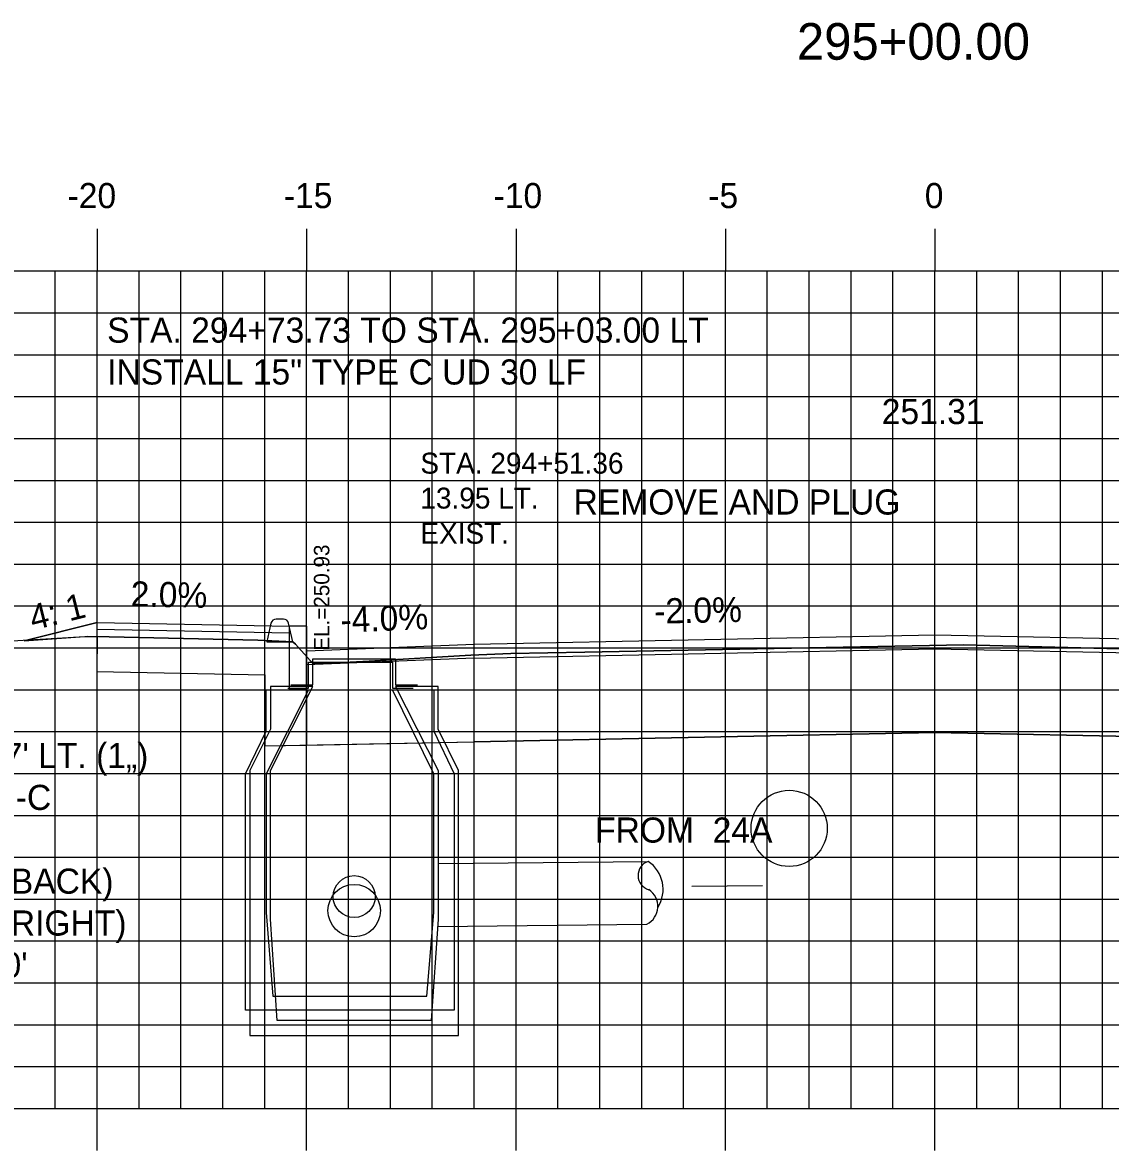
# Model space of a CAD drawing. Extents: x 859352 to 859522, y 366268 to 366378.
# Drawn here: x 859413.35 to 859439.32, y 366306.23 to 366333.17 of the extents above; entities that cross this region are included whole.
import ezdxf

# ---------------------------------------------------------------- set-up
doc = ezdxf.new("R2010")
doc.units = 0
for name, color, linetype in [('ANNOTATION', 7, 'Continuous'), ('D_Curb_Type_1_Lt', 7, 'Continuous'), ('D_Drainage_CB_TypeA1-B1', 7, 'Continuous'), ('D_Drainage_Text', 7, 'Continuous'), ('D_Roadway_Centerline_Text', 7, 'Continuous'), ('D_Roadway_Edge_Shoulder', 7, 'Continuous'), ('D_Roadway_FinishedGrade', 7, 'Continuous'), ('D_Roadway_Sidewalks_Paved', 7, 'Continuous'), ('D_Roadway_SubGrade', 7, 'Continuous'), ('D_Text_Monospaced', 7, 'Continuous'), ('D_Text_Standard', 7, 'Continuous'), ('H_V ANNOTATION', 7, 'Continuous'), ('JUNK COM EXC', 7, 'Continuous'), ('JUNK FILL', 7, 'Continuous'), ('MAJOR', 7, 'Continuous'), ('MINOR', 7, 'Continuous'), ('PDRAIN', 7, 'Continuous'), ('S_Curb_Type_3', 7, 'Continuous'), ('S_Drainage_CB', 7, 'Continuous'), ('S_Roadway_Centerline', 7, 'Continuous')]:
    doc.layers.add(name, color=color, linetype=linetype)

msp = doc.modelspace()

# ---------------------------------------------------------------- linework, layer by layer
at = {"layer": 'ANNOTATION'}
msp.add_line((859431.014, 366312.555), (859429.324, 366312.537), dxfattribs=at)
at = {"layer": 'D_Curb_Type_1_Lt'}
msp.add_lwpolyline([(859419.716, 366318.75), (859419.716, 366317.25), (859420.132, 366317.25), (859420.132, 366318.75)], close=True, dxfattribs=at)
at = {"layer": 'D_Drainage_CB_TypeA1-B1'}
for p, q in [((859419.264, 366317.311), (859419.264, 366316.294)), ((859419.264, 366315.31), (859420.281, 366317.311)), ((859420.281, 366317.311), (859419.264, 366317.311)), ((859423.267, 366317.311), (859422.25, 366317.311)), ((859422.25, 366317.311), (859423.267, 366315.31)), ((859423.267, 366316.294), (859423.267, 366317.311)), ((859419.264, 366316.294), (859418.772, 366315.31)), ((859423.759, 366315.31), (859423.267, 366316.294)), ((859418.772, 366315.31), (859418.772, 366308.976)), ((859419.264, 366311.754), (859419.264, 366315.31)), ((859423.267, 366315.31), (859423.267, 366311.754)), ((859423.759, 366308.976), (859423.759, 366315.31)), ((859419.428, 366309.336), (859419.264, 366311.754)), ((859423.267, 366311.754), (859423.103, 366309.336)), ((859423.103, 366309.336), (859419.428, 366309.336)), ((859418.772, 366308.976), (859423.759, 366308.976))]:
    msp.add_line(p, q, dxfattribs=at)
msp.add_lwpolyline([(859419.756, 366317.353), (859420.281, 366317.353), (859420.281, 366317.976), (859422.25, 366317.976), (859422.25, 366317.353), (859422.775, 366317.353)], dxfattribs=at)
at = {"layer": 'D_Drainage_Text'}
msp.add_circle((859431.651, 366313.925), 0.909, dxfattribs=at)
at = {"layer": 'D_Roadway_Edge_Shoulder'}
msp.add_lwpolyline([(859420.132, 366318.167), (859424.13, 366318.327), (859435.13, 366318.547), (859446.13, 366318.327), (859450.121, 366318.167)], dxfattribs=at)
at = {"layer": 'D_Roadway_FinishedGrade'}
msp.add_line((859413.385, 366318.406), (859415.127, 366318.842), dxfattribs=at)
at = {"layer": 'D_Roadway_Sidewalks_Paved'}
msp.add_lwpolyline([(859415.127, 366318.842), (859419.715, 366318.75), (859419.715, 366318.583), (859415.127, 366318.675)], close=True, dxfattribs=at)
at = {"layer": 'D_Roadway_SubGrade'}
msp.add_lwpolyline([(859415.125, 366318.675), (859415.125, 366317.675), (859419.13, 366317.595), (859419.13, 366315.893), (859420.13, 366315.913)], dxfattribs=at)
for points in [[(859424.13, 366315.993), (859424.13, 366317.993), (859435.13, 366318.213), (859446.13, 366317.993), (859446.13, 366315.993), (859435.13, 366316.213)], [(859424.13, 366317.993), (859420.13, 366317.833), (859420.13, 366315.913), (859424.13, 366315.993)]]:
    msp.add_lwpolyline(points, close=True, dxfattribs=at)
at = {"layer": 'JUNK COM EXC'}
msp.add_lwpolyline([(859415.127, 366318.509), (859415.125, 366317.675), (859419.13, 366317.595), (859419.13, 366315.893), (859424.13, 366315.993), (859435.13, 366316.213), (859446.13, 366315.993), (859451.129, 366315.893), (859451.129, 366317.579), (859445.568, 366318.061), (859444.518, 366318.087), (859435.819, 366318.308), (859426.771, 366318.136), (859425.006, 366318.102), (859424.052, 366318.059), (859421.622, 366317.921), (859421.018, 366317.889), (859420.288, 366317.857), (859419.866, 366318.325), (859419.801, 366318.381), (859418.966, 366318.416), (859415.419, 366318.501), (859415.127, 366318.509)], dxfattribs=at)
at = {"layer": 'JUNK FILL'}
msp.add_lwpolyline([(859415.129, 366318.509), (859415.129, 366318.842), (859415.127, 366318.842), (859413.385, 366318.406), (859414.836, 366318.508), (859415.127, 366318.504), (859415.127, 366318.509)], close=True, dxfattribs=at)
at = {"layer": 'MAJOR'}
for p, q in [((859415.129, 366328.238), (859415.129, 366327.236)), ((859420.129, 366328.238), (859420.129, 366327.236)), ((859425.129, 366328.238), (859425.129, 366327.236)), ((859430.129, 366328.238), (859430.129, 366327.236)), ((859435.129, 366328.238), (859435.129, 366327.236)), ((859365.129, 366327.236), (859505.129, 366327.236)), ((859365.129, 366327.236), (859505.129, 366327.236)), ((859415.129, 366307.236), (859415.129, 366327.236)), ((859420.129, 366307.236), (859420.129, 366327.236)), ((859425.129, 366307.236), (859425.129, 366327.236)), ((859430.129, 366307.236), (859430.129, 366327.236)), ((859435.129, 366307.236), (859435.129, 366327.236)), ((859365.129, 366322.236), (859505.129, 366322.236)), ((859365.129, 366317.236), (859505.129, 366317.236)), ((859365.129, 366312.236), (859505.129, 366312.236)), ((859365.129, 366307.236), (859505.129, 366307.236)), ((859365.129, 366307.236), (859505.129, 366307.236)), ((859415.129, 366306.234), (859415.129, 366307.236)), ((859420.129, 366306.234), (859420.129, 366307.236)), ((859425.129, 366306.234), (859425.129, 366307.236)), ((859430.129, 366306.234), (859430.129, 366307.236)), ((859435.129, 366306.234), (859435.129, 366307.236))]:
    msp.add_line(p, q, dxfattribs=at)
at = {"layer": 'MINOR'}
for p, q in [((859414.129, 366307.236), (859414.129, 366327.236)), ((859416.129, 366307.236), (859416.129, 366327.236)), ((859417.129, 366307.236), (859417.129, 366327.236)), ((859418.129, 366307.236), (859418.129, 366327.236)), ((859419.129, 366307.236), (859419.129, 366327.236)), ((859421.129, 366307.236), (859421.129, 366327.236)), ((859422.129, 366307.236), (859422.129, 366327.236)), ((859423.129, 366307.236), (859423.129, 366327.236)), ((859424.129, 366307.236), (859424.129, 366327.236)), ((859426.129, 366307.236), (859426.129, 366327.236)), ((859427.129, 366307.236), (859427.129, 366327.236)), ((859428.129, 366307.236), (859428.129, 366327.236)), ((859429.129, 366307.236), (859429.129, 366327.236)), ((859431.129, 366307.236), (859431.129, 366327.236)), ((859432.129, 366307.236), (859432.129, 366327.236)), ((859433.129, 366307.236), (859433.129, 366327.236)), ((859434.129, 366307.236), (859434.129, 366327.236)), ((859436.129, 366307.236), (859436.129, 366327.236)), ((859437.129, 366307.236), (859437.129, 366327.236)), ((859438.129, 366307.236), (859438.129, 366327.236)), ((859439.129, 366307.236), (859439.129, 366327.236)), ((859365.129, 366326.236), (859505.129, 366326.236)), ((859365.129, 366325.236), (859505.129, 366325.236)), ((859365.129, 366324.236), (859505.129, 366324.236)), ((859365.129, 366323.236), (859505.129, 366323.236)), ((859365.129, 366321.236), (859505.129, 366321.236)), ((859365.129, 366320.236), (859505.129, 366320.236)), ((859365.129, 366319.236), (859505.129, 366319.236)), ((859365.129, 366318.236), (859505.129, 366318.236)), ((859365.129, 366316.236), (859505.129, 366316.236)), ((859365.129, 366315.236), (859505.129, 366315.236)), ((859365.129, 366314.236), (859505.129, 366314.236)), ((859365.129, 366313.236), (859505.129, 366313.236)), ((859365.129, 366311.236), (859505.129, 366311.236)), ((859365.129, 366310.236), (859505.129, 366310.236)), ((859365.129, 366309.236), (859505.129, 366309.236)), ((859365.129, 366308.236), (859505.129, 366308.236))]:
    msp.add_line(p, q, dxfattribs=at)
at = {"layer": 'PDRAIN'}
for p, q in [((859423.267, 366313.087), (859428.285, 366313.137)), ((859423.255, 366311.586), (859428.255, 366311.636))]:
    msp.add_line(p, q, dxfattribs=at)
for centre, radius in [((859421.265, 366312.296), 0.5), ((859421.265, 366311.961), 0.625)]:
    msp.add_circle(centre, radius, dxfattribs=at)
for centre, radius, start, end in [((859428.397, 366312.801), 0.354, 108.4973, 253.8333), ((859427.838, 366312.47), 0.803, 327.4027, 56.1618), ((859428.037, 366312.062), 0.478, 297.1747, 56.82)]:
    msp.add_arc(centre, radius, start, end, dxfattribs=at)
at = {"layer": 'S_Curb_Type_3'}
for points in [[(859419.279, 366318.826), (859419.176, 366318.381), (859419.801, 366318.381), (859419.699, 366318.826)], [(859419.577, 366318.923), (859419.401, 366318.923)]]:
    msp.add_lwpolyline(points, dxfattribs=at)
for centre, start, end in [((859419.401, 366318.798), 90, 167.0054), ((859419.577, 366318.798), 12.9946, 90)]:
    msp.add_arc(centre, 0.125, start, end, dxfattribs=at)
at = {"layer": 'S_Drainage_CB'}
for p, q in [((859419.16, 366316.248), (859419.16, 366317.233)), ((859419.16, 366317.233), (859420.177, 366317.233)), ((859420.177, 366317.233), (859419.16, 366315.231)), ((859422.179, 366317.233), (859423.163, 366317.233)), ((859423.163, 366315.231), (859422.179, 366317.233)), ((859423.163, 366317.233), (859423.163, 366316.248)), ((859418.668, 366315.231), (859419.16, 366316.248)), ((859423.163, 366316.248), (859423.655, 366315.231)), ((859418.668, 366309.588), (859418.668, 366315.231)), ((859419.16, 366315.231), (859419.16, 366311.918)), ((859423.163, 366311.918), (859423.163, 366315.231)), ((859423.655, 366315.231), (859423.655, 366309.588)), ((859419.16, 366311.918), (859419.324, 366309.916)), ((859422.999, 366309.916), (859423.163, 366311.918)), ((859419.324, 366309.916), (859422.999, 366309.916)), ((859423.655, 366309.588), (859418.668, 366309.588))]:
    msp.add_line(p, q, dxfattribs=at)
msp.add_lwpolyline([(859419.685, 366317.274), (859420.177, 366317.274), (859420.177, 366317.898), (859422.179, 366317.898), (859422.179, 366317.274), (859422.671, 366317.274)], dxfattribs=at)
at = {"layer": 'S_Roadway_Centerline'}
msp.add_lwpolyline([(859412.42, 366318.362), (859414.836, 366318.508), (859414.896, 366318.514), (859415.419, 366318.501), (859418.966, 366318.416), (859419.801, 366318.381), (859419.866, 366318.325), (859420.288, 366317.857), (859421.018, 366317.889), (859421.622, 366317.921), (859424.052, 366318.059), (859425.006, 366318.102), (859426.771, 366318.136), (859435.819, 366318.308), (859444.518, 366318.087), (859445.568, 366318.061), (859451.933, 366317.51), (859452.326, 366317.489), (859453.214, 366317.483), (859453.855, 366318.068), (859453.912, 366318.103), (859458.18, 366317.935), (859464.006, 366317.706), (859478.018, 366317.015)], dxfattribs=at)

# ---------------------------------------------------------------- texts
at = {"layer": 'ANNOTATION'}
for s, rotation, p in [('2.0%', 358.8542, (859415.925, 366319.226)), ('4: 1', 14.0362, (859413.598, 366318.65)), ('-4.0%', 2.2906, (859420.948, 366318.6)), ('-2.0%', 1.1458, (859428.433, 366318.813))]:
    msp.add_text(s, height=0.6, rotation=rotation, dxfattribs=at).set_placement(p)
at = {"layer": 'D_Drainage_Text'}
for s, p in [('STA. 294+73.73 TO STA. 295+03.00 LT', (859415.367, 366325.524)), ('INSTALL 15" TYPE C UD 30 LF', (859415.367, 366324.524)), ("STA. 294+71.73, 13.87' LT. (1„)", (859405.07, 366315.365)), ('INSTALL CB TYPE A1-C', (859405.07, 366314.365)), ('FROM  24A', (859427.016, 366313.585)), ('12" INV. IN = 244.56\' (BACK)', (859405.07, 366312.365)), ('18" INV. IN = 244.35\' (RIGHT)', (859405.07, 366311.365)), ('15" INV. OUT = 244.10\'', (859405.07, 366310.365))]:
    msp.add_text(s, height=0.6, dxfattribs=at).set_placement(p)
at = {"layer": 'D_Roadway_Centerline_Text'}
msp.add_text('251.31', height=0.6, dxfattribs=at).set_placement((859433.861, 366323.579))
at = {"layer": 'D_Text_Monospaced'}
for s, height, p in [('STA. 294+51.36', 0.49998, (859422.845, 366322.396)), ('13.95 LT.', 0.5, (859422.845, 366321.562)), ('EXIST. ', 0.5, (859422.845, 366320.722))]:
    msp.add_text(s, height=height, dxfattribs=at).set_placement(p)
at = {"layer": 'D_Text_Standard'}
msp.add_text('REMOVE AND PLUG', height=0.6, dxfattribs=at).set_placement((859426.504, 366321.419))
msp.add_text(' EL.=250.93', height=0.36848, rotation=90, dxfattribs=at).set_placement((859420.672, 366318.031))
at = {"layer": 'H_V ANNOTATION'}
for s, height, p in [('295+00.00', 0.875, (859431.836, 366332.28)), ('-20', 0.6, (859414.423, 366328.736)), ('-15', 0.6, (859419.586, 366328.736)), ('-10', 0.6, (859424.594, 366328.736)), ('-5', 0.6, (859429.72, 366328.736)), ('0', 0.6, (859434.888, 366328.736))]:
    msp.add_text(s, height=height, dxfattribs=at).set_placement(p)
at = {"layer": 'S_Roadway_Centerline'}
for s, p in [('C', (859435.813, 366318.308)), ('L', (859435.819, 366318.301))]:
    msp.add_text(s, height=0.0146, dxfattribs=at).set_placement(p)

doc.saveas('drawing.dxf')
